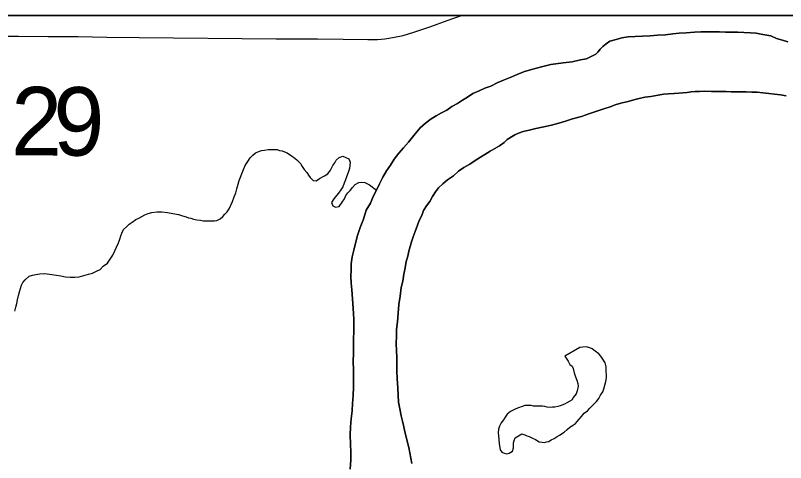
# Model space of a CAD drawing. Extents: x 0 to 64.8, y -5 to 22.
# Drawn here: x 6.975 to 7.614, y 20.529 to 20.9 of the extents above; entities that cross this region are included whole.
import ezdxf

# ---------------------------------------------------------------- set-up
doc = ezdxf.new("R2010")
doc.units = 0
for name, color, linetype in [('GM_X_Adjacent_County', 7, 'Continuous'), ('GM_X_County', 7, 'Continuous'), ('GM_X_Major_River', 7, 'Continuous'), ('GM_X_Minor_Lake', 7, 'Continuous'), ('GM_X_Minor_River', 7, 'Continuous'), ('GM_X_Township', 7, 'Continuous'), ('GM_X_Township_Road', 7, 'Continuous'), ('GM_X_Township_Road_Text', 7, 'Continuous'), ('SH_Data', 7, 'Continuous')]:
    doc.layers.add(name, color=color, linetype=linetype)

msp = doc.modelspace()

# ---------------------------------------------------------------- linework, layer by layer
at = {"layer": 'GM_X_Adjacent_County'}
msp.add_lwpolyline([(8.9, 19.78096), (8.9, 20.9), (2.1, 20.9), (2.1, 19.91762)], dxfattribs=at)
at = {"layer": 'GM_X_County'}
msp.add_lwpolyline([(8.9, 19.78096), (8.9, 20.9), (2.1, 20.9), (2.1, 19.91762)], dxfattribs=at)
at = {"layer": 'GM_X_Major_River'}
for points in [[(7.61553, 20.87813), (7.61098, 20.87934), (7.60606, 20.88094), (7.60153, 20.88291), (7.5947, 20.88416), (7.58939, 20.88538), (7.58445, 20.88546), (7.57913, 20.88592), (7.57419, 20.886), (7.56887, 20.88609), (7.56392, 20.88617), (7.55898, 20.88624), (7.55366, 20.88633), (7.54871, 20.88641), (7.54339, 20.88649), (7.53806, 20.8862), (7.5312, 20.88555), (7.52549, 20.88526), (7.52016, 20.88458), (7.51406, 20.88392), (7.50759, 20.88364), (7.50149, 20.88298), (7.49502, 20.8827), (7.48893, 20.88242), (7.48322, 20.88213), (7.47789, 20.88145), (7.4733, 20.88001), (7.46795, 20.87857), (7.46487, 20.87634), (7.46218, 20.8741), (7.45986, 20.87186), (7.45792, 20.86961), (7.45637, 20.86774), (7.44871, 20.86406), (7.44374, 20.863), (7.43688, 20.86159), (7.42925, 20.86057), (7.41896, 20.85921), (7.41132, 20.85743), (7.40406, 20.85527), (7.39719, 20.85348), (7.39106, 20.85091), (7.38532, 20.84834), (7.37996, 20.84615), (7.3746, 20.84396), (7.36923, 20.84138), (7.36426, 20.83956), (7.35966, 20.83735), (7.3543, 20.83516), (7.35007, 20.83219), (7.34585, 20.82959), (7.34162, 20.827), (7.33702, 20.82441), (7.33278, 20.82144), (7.32857, 20.81923), (7.32396, 20.81664), (7.31974, 20.81405), (7.31512, 20.8107), (7.31087, 20.80659), (7.30661, 20.80172), (7.30118, 20.79496), (7.29692, 20.79009), (7.29304, 20.78559), (7.28916, 20.78071), (7.28604, 20.77582), (7.28292, 20.77093), (7.2798, 20.76566), (7.27705, 20.76038), (7.27469, 20.7551), (7.27194, 20.74983), (7.26957, 20.74416), (7.26606, 20.73852), (7.26366, 20.73096), (7.26089, 20.72416), (7.25888, 20.71735), (7.25726, 20.71092), (7.25565, 20.70524), (7.25442, 20.69956)], [(7.25442, 20.69956), (7.25565, 20.70524), (7.25726, 20.71092), (7.25888, 20.71735), (7.26089, 20.72416), (7.26366, 20.73096), (7.26606, 20.73852), (7.26957, 20.74416), (7.27194, 20.74983), (7.27469, 20.7551), (7.27705, 20.76038), (7.2798, 20.76566), (7.28292, 20.77093), (7.28604, 20.77582), (7.28916, 20.78071), (7.29304, 20.78559), (7.29692, 20.79009), (7.30118, 20.79496), (7.30661, 20.80172), (7.31087, 20.80659), (7.31512, 20.8107), (7.31974, 20.81405), (7.32396, 20.81664), (7.32857, 20.81923), (7.33278, 20.82144), (7.33702, 20.82441), (7.34162, 20.827), (7.34585, 20.82959), (7.35007, 20.83219), (7.3543, 20.83516), (7.35966, 20.83735), (7.36426, 20.83956), (7.36923, 20.84138), (7.3746, 20.84396), (7.37996, 20.84615), (7.38532, 20.84834), (7.39106, 20.85091), (7.39719, 20.85348), (7.40406, 20.85527), (7.41132, 20.85743), (7.41896, 20.85921), (7.42925, 20.86057), (7.43688, 20.86159), (7.44374, 20.863), (7.44871, 20.86406), (7.45637, 20.86774), (7.45792, 20.86961), (7.45986, 20.87186), (7.46218, 20.8741), (7.46487, 20.87634), (7.46795, 20.87857), (7.4733, 20.88001), (7.47789, 20.88145), (7.48322, 20.88213), (7.48893, 20.88242), (7.49502, 20.8827), (7.50149, 20.88298), (7.50759, 20.88364), (7.51406, 20.88392), (7.52016, 20.88458), (7.52549, 20.88526), (7.5312, 20.88555), (7.53806, 20.8862), (7.54339, 20.88649), (7.54871, 20.88641), (7.55366, 20.88633), (7.55898, 20.88624), (7.56392, 20.88617), (7.56887, 20.88609), (7.57419, 20.886), (7.57913, 20.88592), (7.58445, 20.88546), (7.58939, 20.88538), (7.5947, 20.88416), (7.60153, 20.88291), (7.60606, 20.88094), (7.61098, 20.87934), (7.61553, 20.87813)], [(7.30384, 20.52815), (7.30138, 20.54149), (7.30031, 20.54568), (7.29924, 20.55026), (7.29816, 20.55446), (7.29709, 20.55866), (7.29602, 20.56323), (7.29495, 20.56781), (7.2939, 20.57353), (7.29285, 20.57924), (7.29256, 20.58495), (7.29227, 20.59065), (7.29163, 20.59864), (7.29135, 20.60473), (7.29144, 20.61081), (7.29153, 20.61651), (7.29124, 20.62183), (7.29095, 20.62791), (7.29104, 20.634), (7.29113, 20.63931), (7.29199, 20.64576), (7.29248, 20.65297), (7.29298, 20.66019), (7.29422, 20.66701), (7.2951, 20.67421), (7.29632, 20.67951), (7.29717, 20.6852), (7.2984, 20.6905), (7.29924, 20.69581), (7.30045, 20.70035), (7.30128, 20.70452), (7.30248, 20.7083), (7.30368, 20.71208), (7.30489, 20.71624), (7.30648, 20.72077), (7.30846, 20.72606), (7.31005, 20.72984), (7.31201, 20.73398), (7.3136, 20.73814), (7.31594, 20.74191), (7.31866, 20.74566), (7.32101, 20.7498), (7.32335, 20.75357), (7.32607, 20.75694), (7.32954, 20.76031), (7.3334, 20.76367), (7.3384, 20.76701), (7.34264, 20.77074), (7.34687, 20.77371), (7.35186, 20.77667), (7.35647, 20.77964), (7.36877, 20.78742), (7.3726, 20.78965), (7.37644, 20.79186), (7.38029, 20.79446), (7.38299, 20.79708), (7.38645, 20.7993), (7.38914, 20.80078), (7.3922, 20.80225), (7.39603, 20.80371), (7.40099, 20.80477), (7.40672, 20.8062), (7.41321, 20.80762), (7.41969, 20.80903), (7.4258, 20.81046), (7.43116, 20.81227), (7.43689, 20.81408), (7.44453, 20.81624), (7.45065, 20.81842), (7.45715, 20.8206), (7.46289, 20.82241), (7.46824, 20.82423), (7.47321, 20.82604), (7.47818, 20.82749), (7.48314, 20.82855), (7.48773, 20.82999), (7.49231, 20.83106), (7.49689, 20.83213), (7.50185, 20.83281), (7.50795, 20.83385), (7.51253, 20.83454), (7.51671, 20.83485), (7.52128, 20.83516), (7.52509, 20.83548), (7.52852, 20.83581), (7.53195, 20.83613), (7.53538, 20.83646), (7.53881, 20.83678), (7.54223, 20.83673), (7.54642, 20.83704), (7.55212, 20.83695), (7.55592, 20.83689), (7.5601, 20.83682), (7.56429, 20.83676), (7.56847, 20.83669), (7.57228, 20.83663), (7.57646, 20.83656), (7.58102, 20.83649)], [(7.58102, 20.83649), (7.57646, 20.83656), (7.57228, 20.83663), (7.56847, 20.83669), (7.56429, 20.83676), (7.5601, 20.83682), (7.55592, 20.83689), (7.55212, 20.83695), (7.54642, 20.83704), (7.54223, 20.83673), (7.53881, 20.83678), (7.53538, 20.83646), (7.53195, 20.83613), (7.52852, 20.83581), (7.52509, 20.83548), (7.52128, 20.83516), (7.51671, 20.83485), (7.51253, 20.83454), (7.50795, 20.83385), (7.50185, 20.83281), (7.49689, 20.83213), (7.49231, 20.83106), (7.48773, 20.82999), (7.48314, 20.82855), (7.47818, 20.82749), (7.47321, 20.82604), (7.46824, 20.82423), (7.46289, 20.82241), (7.45715, 20.8206), (7.45065, 20.81842), (7.44453, 20.81624), (7.43689, 20.81408), (7.43116, 20.81227), (7.4258, 20.81046), (7.41969, 20.80903), (7.41321, 20.80762), (7.40672, 20.8062), (7.40099, 20.80477), (7.39603, 20.80371), (7.3922, 20.80225), (7.38914, 20.80078), (7.38645, 20.7993), (7.38299, 20.79708), (7.38029, 20.79446), (7.37644, 20.79186), (7.3726, 20.78965), (7.36877, 20.78742), (7.35647, 20.77964), (7.35186, 20.77667), (7.34687, 20.77371), (7.34264, 20.77074), (7.3384, 20.76701), (7.3334, 20.76367), (7.32954, 20.76031), (7.32607, 20.75694), (7.32335, 20.75357), (7.32101, 20.7498), (7.31866, 20.74566), (7.31594, 20.74191), (7.3136, 20.73814), (7.31201, 20.73398), (7.31005, 20.72984), (7.30846, 20.72606), (7.30648, 20.72077), (7.30489, 20.71624), (7.30368, 20.71208), (7.30248, 20.7083), (7.30128, 20.70452), (7.30045, 20.70035), (7.29924, 20.69581), (7.2984, 20.6905), (7.29717, 20.6852), (7.29632, 20.67951), (7.2951, 20.67421), (7.29422, 20.66701), (7.29298, 20.66019), (7.29248, 20.65297), (7.29199, 20.64576), (7.29113, 20.63931), (7.29104, 20.634), (7.29095, 20.62791), (7.29124, 20.62183), (7.29153, 20.61651), (7.29144, 20.61081), (7.29135, 20.60473), (7.29163, 20.59864), (7.29227, 20.59065), (7.29256, 20.58495), (7.29285, 20.57924), (7.2939, 20.57353), (7.29495, 20.56781), (7.29602, 20.56323), (7.29709, 20.55866), (7.29816, 20.55446), (7.29924, 20.55026), (7.30031, 20.54568), (7.30138, 20.54149), (7.30384, 20.52815)], [(7.58102, 20.83649), (7.58558, 20.83642), (7.59015, 20.83635), (7.59471, 20.83589), (7.60951, 20.83414), (7.61406, 20.83331)], [(7.61406, 20.83331), (7.60951, 20.83414), (7.59471, 20.83589), (7.59015, 20.83635), (7.58558, 20.83642), (7.58102, 20.83649)], [(7.25442, 20.69956), (7.25357, 20.69388), (7.25348, 20.68856), (7.25341, 20.68362), (7.2537, 20.67791), (7.25399, 20.67221), (7.25527, 20.65698), (7.25558, 20.65242), (7.25589, 20.64786), (7.25581, 20.64292), (7.25573, 20.6376), (7.25564, 20.6319), (7.25555, 20.6262), (7.25545, 20.61974), (7.25534, 20.6129), (7.25561, 20.60606), (7.25549, 20.59808), (7.25539, 20.59162), (7.25528, 20.58478), (7.25479, 20.57795), (7.25432, 20.57188), (7.25345, 20.56543), (7.25296, 20.5586), (7.25286, 20.55176), (7.25313, 20.54453), (7.25339, 20.53731), (7.2533, 20.53123), (7.2528, 20.52364)], [(7.2528, 20.52364), (7.2533, 20.53123), (7.25339, 20.53731), (7.25313, 20.54453), (7.25286, 20.55176), (7.25296, 20.5586), (7.25345, 20.56543), (7.25432, 20.57188), (7.25479, 20.57795), (7.25528, 20.58478), (7.25539, 20.59162), (7.25549, 20.59808), (7.25561, 20.60606), (7.25534, 20.6129), (7.25545, 20.61974), (7.25555, 20.6262), (7.25564, 20.6319), (7.25573, 20.6376), (7.25581, 20.64292), (7.25589, 20.64786), (7.25558, 20.65242), (7.25527, 20.65698), (7.25399, 20.67221), (7.2537, 20.67791), (7.25341, 20.68362), (7.25348, 20.68856), (7.25357, 20.69388), (7.25442, 20.69956)]]:
    msp.add_lwpolyline(points, dxfattribs=at)
at = {"layer": 'GM_X_Minor_Lake'}
for points in [[(7.43076, 20.61733), (7.43335, 20.61311), (7.43483, 20.61042), (7.43671, 20.60888), (7.43744, 20.60696), (7.43853, 20.60352), (7.43962, 20.60009), (7.44072, 20.59741), (7.44143, 20.59474), (7.44178, 20.59245), (7.44096, 20.58866), (7.44016, 20.58602), (7.43745, 20.58302), (7.43666, 20.58113), (7.43474, 20.58002), (7.43243, 20.57854), (7.43051, 20.57743), (7.42669, 20.57597), (7.42478, 20.57562), (7.42249, 20.5749), (7.42058, 20.57493), (7.41868, 20.57458), (7.41602, 20.575), (7.41413, 20.57541), (7.41223, 20.57582), (7.41033, 20.57585), (7.40843, 20.57588), (7.40653, 20.57591), (7.40462, 20.57594), (7.40273, 20.57635), (7.40007, 20.5764), (7.3974, 20.57644), (7.39013, 20.57351), (7.38783, 20.57241), (7.38553, 20.57131), (7.38284, 20.56907), (7.38128, 20.56681), (7.37972, 20.56456), (7.37778, 20.56193), (7.3766, 20.55929), (7.37579, 20.55664), (7.37537, 20.55361), (7.37571, 20.55132), (7.37604, 20.54828), (7.37636, 20.54447), (7.3767, 20.54143), (7.37705, 20.53952), (7.37854, 20.5376), (7.38043, 20.53681), (7.38232, 20.5364), (7.38461, 20.53674), (7.3873, 20.5386), (7.3881, 20.54124), (7.38817, 20.54542), (7.38858, 20.54732), (7.38938, 20.54958), (7.39514, 20.55291), (7.3974, 20.55212), (7.39929, 20.55133), (7.40118, 20.55054), (7.40383, 20.54935), (7.40647, 20.54817), (7.40948, 20.54622), (7.41176, 20.54581), (7.41366, 20.54578), (7.41557, 20.54613), (7.41748, 20.54648), (7.4194, 20.54797), (7.4217, 20.54907), (7.42439, 20.55055), (7.4263, 20.55166), (7.43015, 20.55426), (7.43247, 20.5565), (7.43478, 20.55836), (7.43708, 20.55984), (7.43939, 20.56133), (7.44094, 20.5632), (7.44249, 20.56508), (7.44443, 20.56733), (7.44675, 20.56995), (7.44944, 20.57181), (7.45138, 20.57406), (7.45293, 20.57593), (7.45486, 20.5778), (7.45679, 20.57967), (7.45874, 20.5823), (7.4603, 20.58494), (7.46224, 20.58757), (7.46304, 20.59021), (7.46466, 20.59627), (7.46509, 20.5993), (7.46513, 20.60196), (7.46479, 20.60425), (7.46482, 20.60653), (7.46485, 20.60843), (7.46414, 20.61186), (7.46229, 20.61493), (7.46043, 20.61724), (7.45893, 20.61916), (7.45593, 20.62149), (7.4533, 20.62343)], [(7.43076, 20.61733), (7.43335, 20.61311), (7.43483, 20.61042), (7.43671, 20.60888), (7.43744, 20.60696), (7.43853, 20.60352), (7.43962, 20.60009), (7.44072, 20.59741), (7.44143, 20.59474), (7.44178, 20.59245), (7.44096, 20.58866), (7.44016, 20.58602), (7.43745, 20.58302), (7.43666, 20.58113), (7.43474, 20.58002), (7.43243, 20.57854), (7.43051, 20.57743), (7.42669, 20.57597), (7.42478, 20.57562), (7.42249, 20.5749), (7.42058, 20.57493), (7.41868, 20.57458), (7.41602, 20.575), (7.41413, 20.57541), (7.41223, 20.57582), (7.41033, 20.57585), (7.40843, 20.57588), (7.40653, 20.57591), (7.40462, 20.57594), (7.40273, 20.57635), (7.40007, 20.5764), (7.3974, 20.57644), (7.39013, 20.57351), (7.38783, 20.57241), (7.38553, 20.57131), (7.38284, 20.56907), (7.38128, 20.56681), (7.37972, 20.56456), (7.37778, 20.56193), (7.3766, 20.55929), (7.37579, 20.55664), (7.37537, 20.55361), (7.37571, 20.55132), (7.37604, 20.54828), (7.37636, 20.54447), (7.3767, 20.54143), (7.37705, 20.53952), (7.37854, 20.5376), (7.38043, 20.53681), (7.38232, 20.5364), (7.38461, 20.53674), (7.3873, 20.5386), (7.3881, 20.54124), (7.38817, 20.54542), (7.38858, 20.54732), (7.38938, 20.54958), (7.39514, 20.55291), (7.3974, 20.55212), (7.39929, 20.55133), (7.40118, 20.55054), (7.40383, 20.54935), (7.40647, 20.54817), (7.40948, 20.54622), (7.41176, 20.54581), (7.41366, 20.54578), (7.41557, 20.54613), (7.41748, 20.54648), (7.4194, 20.54797), (7.4217, 20.54907), (7.42439, 20.55055), (7.4263, 20.55166), (7.43015, 20.55426), (7.43247, 20.5565), (7.43478, 20.55836), (7.43708, 20.55984), (7.43939, 20.56133), (7.44094, 20.5632), (7.44249, 20.56508), (7.44443, 20.56733), (7.44675, 20.56995), (7.44944, 20.57181), (7.45138, 20.57406), (7.45293, 20.57593), (7.45486, 20.5778), (7.45679, 20.57967), (7.45874, 20.5823), (7.4603, 20.58494), (7.46224, 20.58757), (7.46304, 20.59021), (7.46466, 20.59627), (7.46509, 20.5993), (7.46513, 20.60196), (7.46479, 20.60425), (7.46482, 20.60653), (7.46485, 20.60843), (7.46414, 20.61186), (7.46229, 20.61493), (7.46043, 20.61724), (7.45893, 20.61916), (7.45593, 20.62149), (7.4533, 20.62343)], [(7.4533, 20.62343), (7.45141, 20.62422), (7.44876, 20.62502), (7.44571, 20.62469), (7.44304, 20.62435), (7.43076, 20.61733)], [(7.4533, 20.62343), (7.45141, 20.62422), (7.44876, 20.62502), (7.44571, 20.62469), (7.44304, 20.62435), (7.43076, 20.61733)]]:
    msp.add_lwpolyline(points, dxfattribs=at)
at = {"layer": 'GM_X_Minor_River'}
for points in [[(7.02441, 20.68272), (7.02822, 20.68303), (7.03204, 20.68411), (7.03586, 20.68519), (7.0393, 20.68628), (7.04237, 20.68775), (7.04543, 20.68922), (7.04814, 20.69184), (7.0516, 20.69444), (7.05394, 20.69782), (7.05589, 20.70121), (7.06062, 20.7114), (7.06181, 20.71442), (7.06261, 20.71707), (7.0634, 20.71933), (7.06497, 20.72235), (7.06729, 20.72459), (7.06961, 20.72684), (7.07191, 20.72832), (7.07499, 20.73055), (7.07767, 20.73165), (7.07998, 20.73313), (7.08266, 20.73461), (7.08534, 20.7357), (7.08839, 20.73641), (7.09259, 20.73711), (7.09677, 20.73704), (7.10133, 20.73659), (7.10588, 20.73576), (7.11043, 20.73492), (7.11384, 20.73373), (7.11687, 20.73292), (7.11876, 20.73213), (7.12065, 20.73172), (7.12292, 20.73092), (7.12558, 20.7305), (7.12861, 20.73007), (7.13089, 20.72966), (7.13317, 20.72962), (7.13583, 20.72958), (7.13812, 20.72954), (7.1404, 20.7295), (7.14231, 20.72985), (7.14499, 20.73133), (7.1473, 20.73319), (7.14885, 20.73507), (7.15078, 20.73694), (7.15235, 20.73957), (7.15392, 20.74259), (7.1551, 20.74561), (7.15668, 20.74938), (7.15788, 20.75279), (7.15869, 20.75619), (7.15989, 20.75997), (7.1607, 20.763), (7.16427, 20.77206), (7.16584, 20.77546), (7.1678, 20.77885), (7.16975, 20.78186), (7.17206, 20.7841), (7.17438, 20.78597), (7.17706, 20.78706), (7.17935, 20.78778), (7.18164, 20.78813), (7.18469, 20.78884), (7.18735, 20.7888), (7.19001, 20.78875), (7.1923, 20.78872), (7.19418, 20.78793), (7.19646, 20.78751), (7.19835, 20.78672), (7.20062, 20.78593), (7.20401, 20.78359), (7.20589, 20.78242), (7.20852, 20.7801), (7.21151, 20.77701), (7.213, 20.77471), (7.21448, 20.77202), (7.21672, 20.76971), (7.21821, 20.7674), (7.2197, 20.76548), (7.22194, 20.76316), (7.2246, 20.76274), (7.22729, 20.7646), (7.23151, 20.76681), (7.2342, 20.76867), (7.23653, 20.77167), (7.23849, 20.77544), (7.24005, 20.7777), (7.24123, 20.77996), (7.24354, 20.7822), (7.2466, 20.78329), (7.25151, 20.78093), (7.25261, 20.77826), (7.25214, 20.77294), (7.25095, 20.76954), (7.24976, 20.76614), (7.24896, 20.76349), (7.24777, 20.76085), (7.24658, 20.75783), (7.24502, 20.7552)], [(7.24502, 20.7552), (7.24308, 20.75257), (7.24153, 20.75069), (7.2392, 20.74769), (7.23725, 20.74468), (7.23835, 20.742), (7.24061, 20.74083), (7.24367, 20.74154), (7.246, 20.74492), (7.24795, 20.74793), (7.24913, 20.75057), (7.25069, 20.75282), (7.25262, 20.7547), (7.25456, 20.75732), (7.25688, 20.75957), (7.25995, 20.76142), (7.26224, 20.76176), (7.2649, 20.76134), (7.26716, 20.76016), (7.26867, 20.75938), (7.27469, 20.7551)], [(6.9749, 20.65463), (6.97572, 20.65803), (6.97653, 20.66106), (6.97695, 20.6641), (6.97777, 20.6675), (6.97857, 20.67053), (6.97938, 20.67356), (6.98019, 20.6762), (6.98136, 20.67846), (6.9833, 20.68071), (6.98677, 20.6837), (6.98944, 20.68442), (6.99212, 20.68513), (6.99555, 20.68546), (6.99974, 20.68577), (7.00353, 20.68533), (7.00922, 20.68448), (7.01302, 20.68404), (7.01681, 20.68322), (7.02061, 20.68278), (7.02441, 20.68272)]]:
    msp.add_lwpolyline(points, dxfattribs=at)
at = {"layer": 'GM_X_Township'}
msp.add_lwpolyline([(8.9, 19.78096), (8.9, 20.9), (5.7946, 20.9)], dxfattribs=at)
at = {"layer": 'GM_X_Township_Road'}
msp.add_lwpolyline([(6.94289, 20.88272), (6.9777, 20.88272), (7.00256, 20.88238), (7.02742, 20.88238), (7.05105, 20.88202), (7.07777, 20.88173), (7.19153, 20.88068), (7.22572, 20.88047), (7.24687, 20.88018), (7.26736, 20.87988), (7.27539, 20.88006), (7.28153, 20.88057), (7.28944, 20.88181), (7.29665, 20.88344), (7.30555, 20.88608), (7.31968, 20.89077), (7.33311, 20.89566), (7.34509, 20.9)], dxfattribs=at)
at = {"layer": 'SH_Data'}
msp.add_line((2.1, 20.9), (8.9, 20.9), dxfattribs=at)

# ---------------------------------------------------------------- texts
at = {"layer": 'GM_X_Township_Road_Text'}
for s, rotation, p in [('2', 359.69297, (6.97157, 20.78395)), ('9', 359.69859, (7.00657, 20.78376))]:
    msp.add_text(s, height=0.05682, rotation=rotation, dxfattribs=at).set_placement(p)

doc.saveas('drawing.dxf')
